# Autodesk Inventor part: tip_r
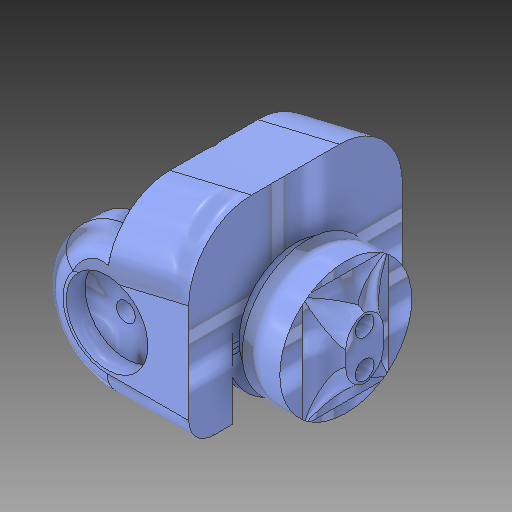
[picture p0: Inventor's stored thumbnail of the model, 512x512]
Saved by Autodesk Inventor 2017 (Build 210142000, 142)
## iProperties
Created: 2017-05
Part Number: tip_r
Material: Generic
Document SubType Name: Modeling
Designer: alez_
Density: 1 g/cm^3
Appearance: Default
Author: alez_
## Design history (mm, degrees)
derived "Tip.ipt" dims "d0" = 11
feature "Solid1::Tip.ipt" dims "d0" = 11
tag "TaggingFeature1"
body "Solid1"
